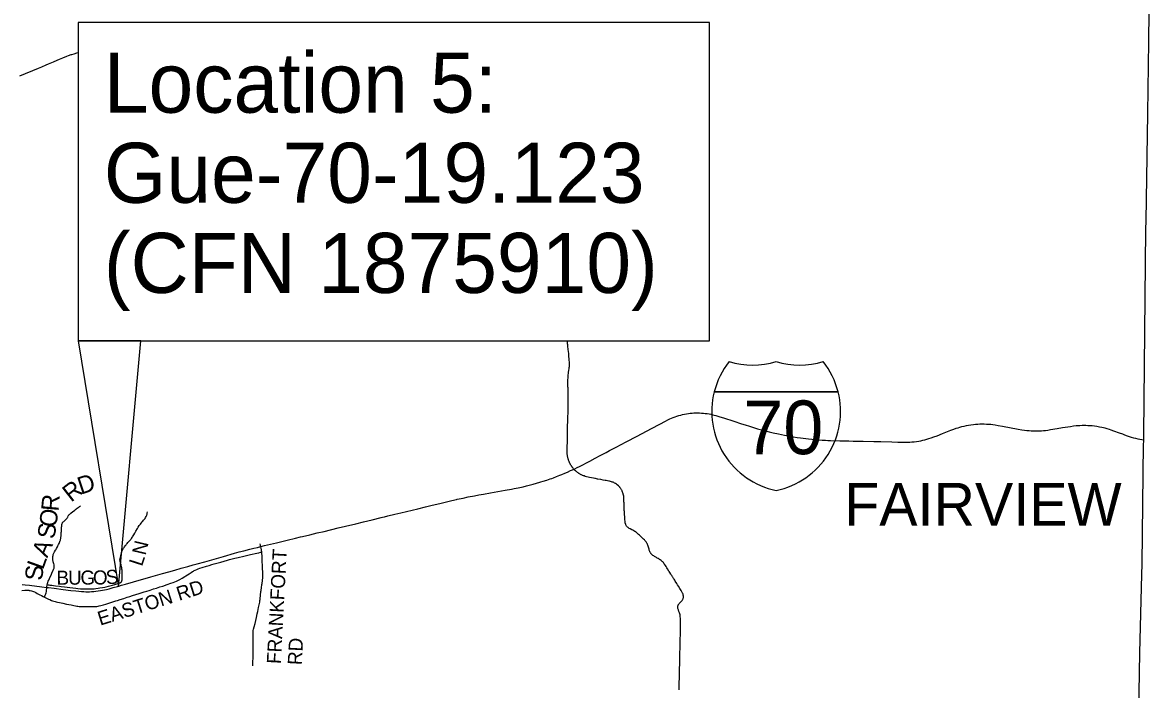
# Model space of a CAD drawing. Extents: x 1761803 to 2441803, y 509895 to 949895.
# Drawn here: x 2271766 to 2324262, y 834521 to 865604 of the extents above; entities that cross this region are included whole.
import ezdxf

# ---------------------------------------------------------------- set-up
doc = ezdxf.new("R2010")
doc.units = 0
for name, color, linetype in [('GM_X_County', 7, 'Continuous'), ('GM_X_County_Road', 7, 'Continuous'), ('GM_X_Minor_Lake', 7, 'Continuous'), ('GM_X_Minor_River', 7, 'Continuous'), ('GM_X_Minor_River_Text', 7, 'Continuous'), ('GM_X_State_Location', 7, 'Continuous'), ('GM_X_Unincorporated_Location', 7, 'Continuous')]:
    doc.layers.add(name, color=color, linetype=linetype)

msp = doc.modelspace()

# ---------------------------------------------------------------- linework, layer by layer
at = {"layer": 'GM_X_County'}
msp.add_lwpolyline([(2324262, 868851), (2324216, 864717), (2324176, 861362), (2324107, 857362), (2324092, 856384), (2324078, 855960), (2323982, 846407), (2323980, 846235), (2323977, 846057), (2323976, 845974), (2323909, 840366), (2323897, 839881), (2323804, 836223), (2323694, 829731)], dxfattribs=at)
at = {"layer": 'GM_X_County_Road'}
for points in [[(2272918, 839399), (2272918, 839399), (2272932, 839462), (2272946, 839509), (2272964, 839561), (2272986, 839619), (2273017, 839692), (2273109, 839895), (2273134, 839948), (2273197, 840077), (2273215, 840119), (2273228, 840153), (2273236, 840178), (2273240, 840201), (2273243, 840227), (2273244, 840253), (2273243, 840279), (2273239, 840305), (2273233, 840334), (2273218, 840391), (2273213, 840409), (2273209, 840422), (2273198, 840465), (2273192, 840493), (2273185, 840538), (2273180, 840580), (2273178, 840616), (2273177, 840649), (2273178, 840685), (2273181, 840721), (2273188, 840766), (2273196, 840804), (2273206, 840839), (2273220, 840872), (2273237, 840904), (2273262, 840943), (2273306, 841008), (2273322, 841033), (2273331, 841050), (2273338, 841061), (2273353, 841090), (2273388, 841167), (2273413, 841217), (2273440, 841272), (2273467, 841329), (2273502, 841410), (2273521, 841458), (2273530, 841486), (2273538, 841521), (2273546, 841560), (2273549, 841586), (2273552, 841605), (2273559, 841674), (2273566, 841762), (2273572, 841844), (2273575, 841890), (2273576, 841909), (2273576, 841922), (2273577, 841939), (2273581, 842007), (2273583, 842023), (2273586, 842050), (2273587, 842063), (2273588, 842079), (2273588, 842085), (2273589, 842092), (2273591, 842128), (2273597, 842190), (2273602, 842219), (2273608, 842241), (2273615, 842263), (2273625, 842284), (2273635, 842300), (2273647, 842316), (2273663, 842333), (2273685, 842353), (2273729, 842392), (2273765, 842425), (2273797, 842458), (2273823, 842487), (2273841, 842510), (2273855, 842532), (2273870, 842557), (2273898, 842610), (2273909, 842629), (2273924, 842651), (2273943, 842674), (2273963, 842696), (2273982, 842713), (2274013, 842738), (2274117, 842818), (2274180, 842864), (2274214, 842890), (2274227, 842899), (2274235, 842905), (2274240, 842908), (2274254, 842918), (2274267, 842928), (2274316, 842965), (2274332, 842976), (2274348, 842988), (2274361, 842997), (2274374, 843007), (2274392, 843020), (2274427, 843048), (2274463, 843076)], [(2276338, 839508), (2276350, 839517), (2276362, 839528), (2276373, 839541), (2276383, 839558), (2276392, 839575), (2276399, 839597), (2276405, 839619), (2276408, 839642), (2276408, 839668), (2276408, 839701), (2276411, 839780), (2276413, 839845), (2276413, 839894), (2276412, 839943), (2276410, 839996), (2276406, 840044), (2276401, 840087), (2276395, 840135), (2276387, 840184), (2276378, 840235), (2276368, 840277), (2276355, 840324), (2276338, 840380), (2276324, 840434), (2276314, 840475), (2276307, 840513), (2276304, 840542), (2276305, 840572), (2276307, 840598), (2276312, 840630), (2276322, 840672), (2276346, 840760), (2276364, 840820), (2276382, 840882), (2276393, 840920), (2276411, 840982), (2276423, 841016), (2276431, 841041), (2276441, 841062), (2276451, 841079), (2276471, 841108), (2276495, 841140), (2276520, 841174), (2276554, 841218), (2276578, 841248), (2276591, 841263), (2276614, 841291), (2276639, 841321), (2276678, 841369), (2276703, 841399), (2276733, 841434), (2276763, 841469), (2276807, 841517), (2276826, 841540), (2276845, 841563), (2276870, 841597), (2276893, 841633), (2276947, 841730), (2276990, 841804), (2277044, 841894), (2277125, 842029), (2277157, 842082), (2277206, 842160), (2277230, 842195), (2277257, 842232), (2277293, 842279), (2277334, 842329), (2277366, 842366), (2277407, 842413), (2277428, 842438), (2277448, 842464), (2277472, 842495), (2277494, 842531), (2277520, 842577), (2277538, 842612), (2277549, 842639), (2277558, 842667), (2277565, 842696), (2277571, 842735), (2277580, 842800), (2277580, 842806)], [(2282910, 840926), (2282909, 840939), (2282907, 840951), (2282905, 840976), (2282902, 840992), (2282899, 841011), (2282897, 841021), (2282896, 841024), (2282894, 841039), (2282887, 841071), (2282887, 841073), (2282882, 841097), (2282862, 841180), (2282856, 841203), (2282848, 841241), (2282831, 841313)], [(2274576, 838387), (2274720, 838386), (2274808, 838384), (2275038, 838383), (2275116, 838384), (2275171, 838388), (2275230, 838394), (2275288, 838402), (2275342, 838413), (2275406, 838429), (2275532, 838463), (2275642, 838496), (2275784, 838539), (2276024, 838617), (2276118, 838647), (2276183, 838667), (2276320, 838713), (2276486, 838766), (2276642, 838817), (2276770, 838857), (2276896, 838895), (2277195, 838992), (2277336, 839036), (2277430, 839066), (2277555, 839105), (2277665, 839138), (2277711, 839154), (2277782, 839178), (2277867, 839206), (2278007, 839250), (2278167, 839302), (2278298, 839343), (2278510, 839411), (2278675, 839468), (2278776, 839505), (2278864, 839541), (2278939, 839574), (2279057, 839631), (2279100, 839654), (2279195, 839707), (2279321, 839782), (2279374, 839815), (2279445, 839862), (2279526, 839918), (2279619, 839978), (2279681, 840016), (2279724, 840041), (2279768, 840063), (2279815, 840086), (2279878, 840113), (2279949, 840141), (2280026, 840169), (2280129, 840202), (2280334, 840263), (2280460, 840299), (2280588, 840338), (2280699, 840371), (2280878, 840423), (2281004, 840459), (2281165, 840505), (2281307, 840546), (2281412, 840574), (2281539, 840606), (2281654, 840634), (2281804, 840668), (2282071, 840732), (2282381, 840805), (2282687, 840876), (2282773, 840895), (2282853, 840913), (2282910, 840926)], [(2282490, 835621), (2282494, 835714), (2282496, 835777), (2282499, 835829), (2282501, 835875), (2282503, 835934), (2282503, 835963), (2282504, 836006), (2282508, 836176), (2282509, 836258), (2282510, 836395), (2282510, 836514), (2282510, 836599), (2282511, 836720), (2282513, 836832), (2282513, 836901), (2282510, 837002), (2282505, 837104), (2282504, 837163), (2282506, 837193), (2282510, 837232), (2282516, 837268), (2282532, 837335), (2282559, 837447), (2282596, 837603), (2282659, 837875), (2282699, 838041), (2282724, 838153), (2282765, 838349), (2282790, 838471), (2282803, 838532), (2282814, 838593), (2282819, 838625), (2282825, 838674), (2282830, 838713), (2282836, 838765), (2282839, 838797), (2282846, 838862), (2282851, 838904), (2282857, 838950), (2282869, 839057), (2282873, 839083), (2282879, 839132), (2282883, 839157), (2282888, 839193), (2282893, 839228), (2282898, 839264), (2282901, 839280), (2282904, 839306), (2282912, 839364), (2282917, 839400), (2282920, 839419), (2282927, 839464), (2282929, 839481), (2282933, 839516), (2282939, 839549), (2282943, 839588), (2282947, 839617), (2282948, 839623), (2282951, 839662), (2282954, 839695), (2282957, 839730), (2282959, 839789), (2282959, 839841), (2282958, 839927), (2282956, 840011), (2282951, 840138), (2282942, 840319), (2282934, 840465), (2282930, 840563), (2282927, 840634), (2282926, 840684), (2282925, 840739), (2282923, 840769), (2282919, 840837), (2282916, 840872), (2282915, 840887), (2282914, 840896), (2282913, 840908), (2282911, 840920), (2282910, 840926)], [(2272788, 838827), (2272828, 838911), (2272842, 838947), (2272854, 838985), (2272865, 839029), (2272876, 839080), (2272884, 839132), (2272888, 839169), (2272895, 839223), (2272901, 839280), (2272905, 839315), (2272915, 839383), (2272918, 839399)], [(2272918, 839399), (2272991, 839395), (2273043, 839389), (2273138, 839376), (2273212, 839367), (2273303, 839356), (2273482, 839335), (2273567, 839326), (2273723, 839305), (2273967, 839276), (2274110, 839257), (2274253, 839239), (2274347, 839228), (2274462, 839217), (2274553, 839211), (2274661, 839207), (2274750, 839205), (2274816, 839206), (2274920, 839209), (2275012, 839213), (2275097, 839219), (2275179, 839227), (2275286, 839240), (2275373, 839253), (2275493, 839274), (2275595, 839295), (2275662, 839310), (2275777, 839340), (2275957, 839389), (2276067, 839419), (2276213, 839458), (2276263, 839473), (2276294, 839484), (2276318, 839495), (2276337, 839507), (2276338, 839508)], [(2271735, 839138), (2271866, 839149), (2271918, 839152), (2271961, 839153), (2272010, 839150), (2272053, 839145), (2272082, 839140), (2272124, 839130), (2272185, 839114), (2272235, 839099), (2272275, 839084), (2272321, 839065), (2272386, 839034), (2272454, 839000), (2272579, 838936), (2272645, 838900), (2272729, 838856), (2272788, 838827)], [(2272788, 838827), (2272884, 838778), (2272913, 838764), (2272973, 838736), (2273032, 838708), (2273110, 838674), (2273162, 838654), (2273226, 838631), (2273280, 838615), (2273330, 838602), (2273397, 838587), (2273494, 838568), (2273568, 838553), (2273645, 838537), (2273818, 838503), (2274037, 838460), (2274150, 838438), (2274240, 838420), (2274291, 838410), (2274343, 838402), (2274401, 838395), (2274467, 838391), (2274576, 838387)]]:
    msp.add_lwpolyline(points, dxfattribs=at)
at = {"layer": 'GM_X_Minor_Lake'}
for points in [[(2297141, 845831), (2297141, 845844), (2297142, 845886), (2297143, 845911), (2297145, 845983), (2297145, 846025), (2297146, 846071), (2297147, 846171), (2297147, 846250), (2297147, 846282), (2297147, 846309), (2297147, 846333), (2297147, 846350), (2297147, 846385), (2297147, 846403), (2297147, 846426), (2297147, 846469), (2297147, 846486), (2297150, 846604), (2297152, 846692), (2297155, 846749), (2297159, 846838), (2297164, 846974), (2297171, 847151), (2297175, 847288), (2297178, 847349), (2297179, 847386), (2297180, 847427), (2297182, 847488), (2297181, 847507), (2297181, 847574), (2297180, 847633), (2297179, 847754), (2297178, 847842), (2297177, 847915), (2297177, 848019), (2297177, 848108), (2297177, 848164), (2297177, 848285), (2297177, 848390), (2297176, 848514), (2297176, 848580), (2297175, 848633), (2297172, 848724), (2297171, 848809), (2297172, 848862), (2297175, 848944), (2297181, 849038), (2297188, 849120), (2297206, 849306), (2297216, 849394), (2297228, 849481), (2297233, 849510), (2297235, 849527), (2297242, 849572), (2297248, 849624), (2297251, 849670), (2297251, 849712), (2297247, 849766), (2297236, 849879), (2297229, 849945), (2297222, 850024), (2297218, 850069), (2297214, 850125), (2297207, 850188), (2297200, 850258), (2297198, 850280), (2297190, 850352), (2297188, 850371), (2297183, 850410), (2297175, 850472), (2297172, 850494), (2297167, 850533), (2297164, 850559), (2297162, 850572), (2297160, 850591), (2297158, 850613), (2297154, 850642), (2297153, 850666), (2297151, 850696), (2297151, 850719), (2297151, 850740), (2297153, 850772)], [(2297291, 845006), (2297279, 845027), (2297270, 845048), (2297258, 845071), (2297250, 845089), (2297241, 845110), (2297234, 845128), (2297226, 845149), (2297205, 845208), (2297195, 845235), (2297188, 845260), (2297179, 845292), (2297172, 845320), (2297164, 845352), (2297158, 845384), (2297152, 845416), (2297148, 845445), (2297144, 845477), (2297141, 845510), (2297139, 845536), (2297139, 845548), (2297138, 845570), (2297138, 845604), (2297138, 845637), (2297139, 845670), (2297139, 845706), (2297140, 845731), (2297139, 845767), (2297140, 845812), (2297141, 845831)], [(2297603, 844647), (2297568, 844675), (2297539, 844701), (2297534, 844705), (2297522, 844716), (2297486, 844749), (2297475, 844761), (2297450, 844789), (2297446, 844792), (2297437, 844802), (2297434, 844807), (2297415, 844830), (2297397, 844852), (2297383, 844870), (2297375, 844881), (2297363, 844896), (2297348, 844917), (2297343, 844924), (2297333, 844938), (2297319, 844960), (2297305, 844982), (2297292, 845005), (2297291, 845006)], [(2297716, 844570), (2297695, 844582), (2297681, 844591), (2297651, 844611), (2297620, 844634), (2297603, 844647)], [(2299777, 843439), (2299776, 843454), (2299774, 843489), (2299769, 843535), (2299762, 843579), (2299752, 843619), (2299746, 843642), (2299733, 843683), (2299719, 843723), (2299703, 843762), (2299699, 843771), (2299694, 843780), (2299677, 843810), (2299672, 843819), (2299653, 843852), (2299636, 843879), (2299616, 843907), (2299616, 843908), (2299594, 843934), (2299583, 843948), (2299559, 843976), (2299529, 844006), (2299470, 844058), (2299438, 844082), (2299434, 844085), (2299384, 844117), (2299347, 844140), (2299325, 844151), (2299305, 844161), (2299273, 844176), (2299240, 844188), (2299205, 844199), (2299162, 844211), (2299113, 844223), (2299071, 844232), (2299020, 844242), (2298961, 844253), (2298911, 844263), (2298815, 844281), (2298711, 844300), (2298571, 844326), (2298549, 844330), (2298504, 844338), (2298462, 844346), (2298420, 844354), (2298370, 844364), (2298272, 844384), (2298178, 844402), (2298109, 844417), (2298030, 844435), (2297981, 844449), (2297922, 844470), (2297898, 844479), (2297858, 844494), (2297834, 844507), (2297812, 844517), (2297786, 844531), (2297758, 844545), (2297740, 844555), (2297716, 844570)], [(2302368, 835174), (2302372, 835336), (2302377, 835565), (2302378, 835641), (2302380, 835729), (2302381, 835770), (2302383, 835860), (2302384, 835997), (2302388, 836158), (2302392, 836297), (2302395, 836381), (2302397, 836475), (2302399, 836554), (2302400, 836645), (2302405, 836815), (2302406, 836894), (2302408, 836946), (2302409, 837012), (2302410, 837075), (2302412, 837193), (2302418, 837415), (2302420, 837507), (2302419, 837592), (2302421, 837687), (2302421, 837749), (2302420, 837792), (2302416, 837850), (2302408, 837909), (2302402, 837952), (2302393, 838000), (2302380, 838053), (2302366, 838097), (2302345, 838153), (2302317, 838227), (2302304, 838265), (2302295, 838301), (2302290, 838321), (2302287, 838353), (2302289, 838377), (2302290, 838394), (2302297, 838418), (2302304, 838441), (2302314, 838465), (2302326, 838488), (2302336, 838504), (2302352, 838525), (2302376, 838550), (2302426, 838598), (2302454, 838623), (2302478, 838647), (2302501, 838675), (2302517, 838699), (2302529, 838724), (2302537, 838748), (2302544, 838775), (2302549, 838800), (2302550, 838826), (2302551, 838857), (2302549, 838884), (2302546, 838907), (2302544, 838917), (2302540, 838937), (2302537, 838947), (2302533, 838963), (2302527, 838978), (2302520, 838995), (2302514, 839007), (2302501, 839034), (2302477, 839076), (2302443, 839132), (2302387, 839221), (2302321, 839328), (2302278, 839396), (2302244, 839453), (2302168, 839575), (2302145, 839611), (2302116, 839660), (2302097, 839690), (2302077, 839724), (2302061, 839748), (2302044, 839776), (2302011, 839829), (2301985, 839869), (2301969, 839896), (2301916, 839980), (2301890, 840021), (2301875, 840042), (2301815, 840137), (2301778, 840196), (2301747, 840246), (2301717, 840295), (2301673, 840361), (2301647, 840399), (2301618, 840434), (2301591, 840464), (2301560, 840492), (2301532, 840515), (2301508, 840534), (2301471, 840558), (2301445, 840576), (2301422, 840590), (2301376, 840618), (2301333, 840644), (2301293, 840668), (2301203, 840724), (2301172, 840744), (2301135, 840769), (2301096, 840800), (2301083, 840811), (2301056, 840838), (2301049, 840846), (2301036, 840863), (2301028, 840873), (2301020, 840886), (2301000, 840920), (2300995, 840930), (2300994, 840933), (2300991, 840939), (2300987, 840949), (2300977, 840976), (2300963, 841017), (2300949, 841061), (2300936, 841108), (2300924, 841151), (2300911, 841197), (2300896, 841242), (2300880, 841283), (2300864, 841317), (2300855, 841336), (2300837, 841368), (2300831, 841378), (2300809, 841408), (2300784, 841440), (2300758, 841468), (2300736, 841491), (2300699, 841528), (2300666, 841559), (2300588, 841630), (2300523, 841690), (2300506, 841705), (2300458, 841750), (2300440, 841765), (2300409, 841794), (2300382, 841817), (2300372, 841826), (2300359, 841837), (2300333, 841861), (2300285, 841891), (2300246, 841916), (2300198, 841941), (2300150, 841965), (2300074, 842002), (2300027, 842026), (2299994, 842047), (2299972, 842063), (2299943, 842090), (2299919, 842116), (2299903, 842136), (2299887, 842163), (2299874, 842190), (2299862, 842218), (2299854, 842244), (2299852, 842251), (2299848, 842265), (2299845, 842279), (2299840, 842308), (2299837, 842323), (2299834, 842354), (2299826, 842446), (2299823, 842493), (2299821, 842522), (2299819, 842545), (2299818, 842562), (2299809, 842679), (2299806, 842722), (2299804, 842751), (2299801, 842813), (2299798, 842864), (2299794, 842975), (2299791, 843063), (2299787, 843165), (2299787, 843189), (2299785, 843224), (2299784, 843265), (2299783, 843305), (2299781, 843351), (2299780, 843392), (2299779, 843408), (2299777, 843439)], [(2302352, 834497), (2302361, 834861), (2302365, 835035), (2302367, 835160), (2302368, 835174)]]:
    msp.add_lwpolyline(points, dxfattribs=at)
at = {"layer": 'GM_X_Minor_River'}
msp.add_lwpolyline([(2271744, 839420), (2271884, 839405), (2272083, 839381), (2272665, 839309), (2272901, 839280), (2272978, 839271), (2273235, 839239), (2273655, 839186), (2274023, 839141), (2274254, 839112), (2274391, 839097), (2274509, 839087), (2274617, 839081), (2274716, 839077), (2274805, 839076), (2274893, 839078), (2274982, 839082), (2275080, 839089), (2275185, 839099), (2275296, 839112), (2275393, 839127), (2275484, 839143), (2275577, 839162), (2275682, 839187), (2275797, 839217), (2275990, 839270), (2276185, 839326), (2276378, 839380), (2276564, 839433), (2276930, 839537), (2277738, 839765), (2278293, 839923), (2278577, 840004), (2278859, 840083), (2279159, 840168), (2279461, 840254), (2279711, 840323), (2279907, 840378), (2280251, 840476), (2281131, 840724), (2281646, 840871), (2281864, 840931), (2282076, 840987), (2282349, 841056), (2282544, 841103), (2282716, 841144), (2282862, 841180), (2283044, 841224), (2283319, 841291), (2283603, 841358), (2283839, 841415), (2284212, 841506), (2284358, 841541), (2284483, 841571), (2284719, 841629), (2284811, 841651), (2285153, 841732), (2285497, 841816), (2285810, 841890), (2286463, 842048), (2286808, 842132), (2287286, 842247), (2287653, 842335), (2288048, 842431), (2288466, 842531), (2288539, 842550), (2288541, 842550), (2288635, 842573), (2288785, 842609), (2289113, 842688), (2289381, 842753), (2289655, 842820), (2290182, 842946), (2290536, 843031), (2290842, 843105), (2291205, 843192), (2291518, 843269), (2291767, 843328), (2291984, 843378), (2292011, 843384), (2292285, 843444), (2292529, 843494), (2292822, 843551), (2293019, 843587), (2293245, 843627), (2293565, 843684), (2294250, 843807), (2294547, 843861), (2294666, 843883), (2294856, 843922), (2295080, 843970), (2295240, 844006), (2295374, 844039), (2295555, 844087), (2295713, 844132), (2295858, 844175), (2295914, 844192), (2296024, 844226), (2296189, 844280), (2296351, 844335), (2296422, 844361), (2296493, 844387), (2296643, 844444), (2296789, 844502), (2296890, 844543), (2297032, 844602), (2297153, 844655), (2297299, 844720), (2297392, 844762), (2297450, 844789), (2297490, 844808), (2297603, 844862), (2297711, 844916), (2298191, 845168), (2298443, 845301), (2298678, 845425), (2298762, 845469), (2298947, 845568), (2299107, 845652), (2299414, 845814), (2299881, 846061), (2300391, 846330), (2301067, 846686), (2301449, 846888), (2301716, 847029), (2301830, 847087), (2301918, 847130), (2301999, 847165), (2302078, 847197), (2302161, 847228), (2302248, 847258), (2302338, 847286), (2302427, 847310), (2302516, 847332), (2302602, 847351), (2302692, 847368), (2302783, 847382), (2302867, 847393), (2302952, 847402), (2303037, 847408), (2303128, 847411), (2303213, 847411), (2303295, 847410), (2303390, 847405), (2303481, 847399), (2303566, 847390), (2303657, 847378), (2303744, 847364), (2303831, 847348), (2303921, 847328), (2303990, 847310), (2304056, 847291), (2304242, 847235), (2304426, 847177), (2304897, 847023), (2305259, 846908), (2305431, 846852), (2305637, 846785), (2305821, 846727), (2306001, 846674), (2306184, 846623), (2306377, 846571), (2306540, 846530), (2306731, 846485), (2306987, 846428), (2307119, 846400), (2307264, 846372), (2307367, 846353), (2307500, 846329), (2307684, 846297), (2307846, 846271), (2308012, 846248), (2308256, 846217), (2308386, 846202), (2308530, 846187), (2308827, 846160), (2309017, 846145), (2309178, 846134), (2309276, 846129), (2309407, 846124), (2309840, 846114), (2310250, 846105), (2310463, 846100), (2310719, 846095), (2310919, 846089), (2311427, 846078), (2311752, 846070), (2312260, 846058), (2312546, 846051), (2312752, 846047), (2312884, 846045), (2312992, 846047), (2313097, 846051), (2313199, 846059), (2313300, 846069), (2313407, 846083), (2313511, 846100), (2313605, 846116), (2313702, 846136), (2313794, 846158), (2313890, 846183), (2313987, 846212), (2314090, 846246), (2314211, 846289), (2314367, 846349), (2314621, 846448), (2315008, 846600), (2315153, 846655), (2315258, 846692), (2315351, 846722), (2315433, 846747), (2315521, 846771), (2315629, 846798), (2315735, 846821), (2315838, 846840), (2315948, 846857), (2316058, 846871), (2316163, 846882), (2316261, 846889), (2316359, 846894), (2316457, 846896), (2316558, 846895), (2316663, 846892), (2316761, 846887), (2316872, 846878), (2316970, 846866), (2317080, 846850), (2317209, 846829), (2317410, 846793), (2318152, 846656), (2318320, 846626), (2318440, 846608), (2318547, 846595), (2318652, 846585), (2318750, 846578), (2318862, 846573), (2318974, 846571), (2319062, 846572), (2319148, 846575), (2319233, 846580), (2319321, 846587), (2319416, 846598), (2319523, 846612), (2319657, 846632), (2319967, 846684), (2320207, 846724), (2320582, 846784), (2320719, 846803), (2320842, 846818), (2320940, 846826), (2321025, 846831), (2321125, 846834), (2321186, 846834), (2321257, 846834), (2321299, 846834), (2321394, 846831), (2321489, 846825), (2321596, 846816), (2321707, 846803), (2321817, 846786), (2321939, 846765), (2322036, 846745), (2322119, 846726), (2322182, 846709), (2322270, 846684), (2322380, 846650), (2322460, 846623), (2322584, 846579), (2322847, 846486), (2323004, 846428), (2323093, 846395), (2323229, 846346), (2323322, 846314), (2323413, 846286), (2323517, 846255), (2323615, 846229), (2323721, 846204), (2323817, 846184), (2323901, 846168), (2323973, 846157)], dxfattribs=at)
at = {"layer": 'GM_X_Minor_River_Text'}
msp.add_lwpolyline([(2271645, 863120), (2272504, 863479), (2272665, 863545), (2272864, 863629), (2272970, 863675), (2273205, 863774), (2273381, 863847), (2273495, 863896), (2273649, 863961), (2273828, 864033), (2273911, 864064), (2274036, 864107), (2274055, 864114), (2274166, 864150), (2274290, 864188), (2274363, 864209)], dxfattribs=at)
at = {"layer": 'GM_X_State_Location'}
for points in [[(2274363, 850777), (2303767, 850777), (2303767, 865601), (2274363, 865601)], [(2276235, 839309), (2277279, 850772), (2274363, 850772)]]:
    msp.add_lwpolyline(points, close=True, dxfattribs=at)
at = {"layer": 'GM_X_Unincorporated_Location'}
for p, q in [((2303986, 848393), (2309757, 848393)), ((2309757, 848393), (2303986, 848393)), ((2309757, 848393), (2303986, 848393))]:
    msp.add_line(p, q, dxfattribs=at)
for centre, start, end in [((2307622, 847473), 141.669, 165.8066), ((2305776, 853385), 253.0091, 286.9909), ((2307967, 853385), 253.0091, 286.9909), ((2306122, 847473), 14.1934, 38.331), ((2307622, 847473), 165.8066, 258.463), ((2306122, 847473), 281.537, 14.1934)]:
    msp.add_arc(centre, 3750, start, end, dxfattribs=at)

# ---------------------------------------------------------------- texts
at = {"layer": 'GM_X_County_Road'}
for s, height, rotation, p in [('R', 810, 37.9806, (2274026, 843223)), ('D', 810, 18.4304, (2274486, 843598)), ('FAIRVIEW', 2000, 0, (2310040, 842149)), ('R', 810, 84.8805, (2273436, 842802)), ('O', 810, 81.805, (2273329, 842049)), ('S', 810, 82.5189, (2273258, 841510)), ('A', 810, 67.0084, (2272917, 840624)), ('N', 656, 76.5389, (2277496, 840746)), ('FRANKFORT', 656.1, 86.9838, (2283796, 835698)), ('L', 810, 70.2369, (2272716, 840065)), ('L', 656, 72.2561, (2277332, 840228)), ('S', 810, 86.31, (2272693, 839578)), ('B', 656, 0.3436, (2273351, 839400)), ('U', 656, 0.3443, (2273890, 839403)), ('G', 656, 0.348, (2274467, 839407)), ('O', 656, 0.704, (2275049, 839410)), ('S', 656, 4.2355, (2275671, 839419)), ('EASTON RD', 656.1, 17.48, (2275384, 837491)), ('RD', 656.1, 86.9838, (2284771, 835646))]:
    msp.add_text(s, height=height, rotation=rotation, dxfattribs=at).set_placement(p)
at = {"layer": 'GM_X_State_Location'}
for s, p in [('Location 5:', (2275554, 861401)), ('Gue-70-19.123', (2275554, 857201)), ('(CFN 1875910)', (2275554, 853001))]:
    msp.add_text(s, height=2800, dxfattribs=at).set_placement(p)
at = {"layer": 'GM_X_Unincorporated_Location'}
msp.add_text('70', height=2500, dxfattribs=at).set_placement((2305347, 845487))

doc.saveas('drawing.dxf')
